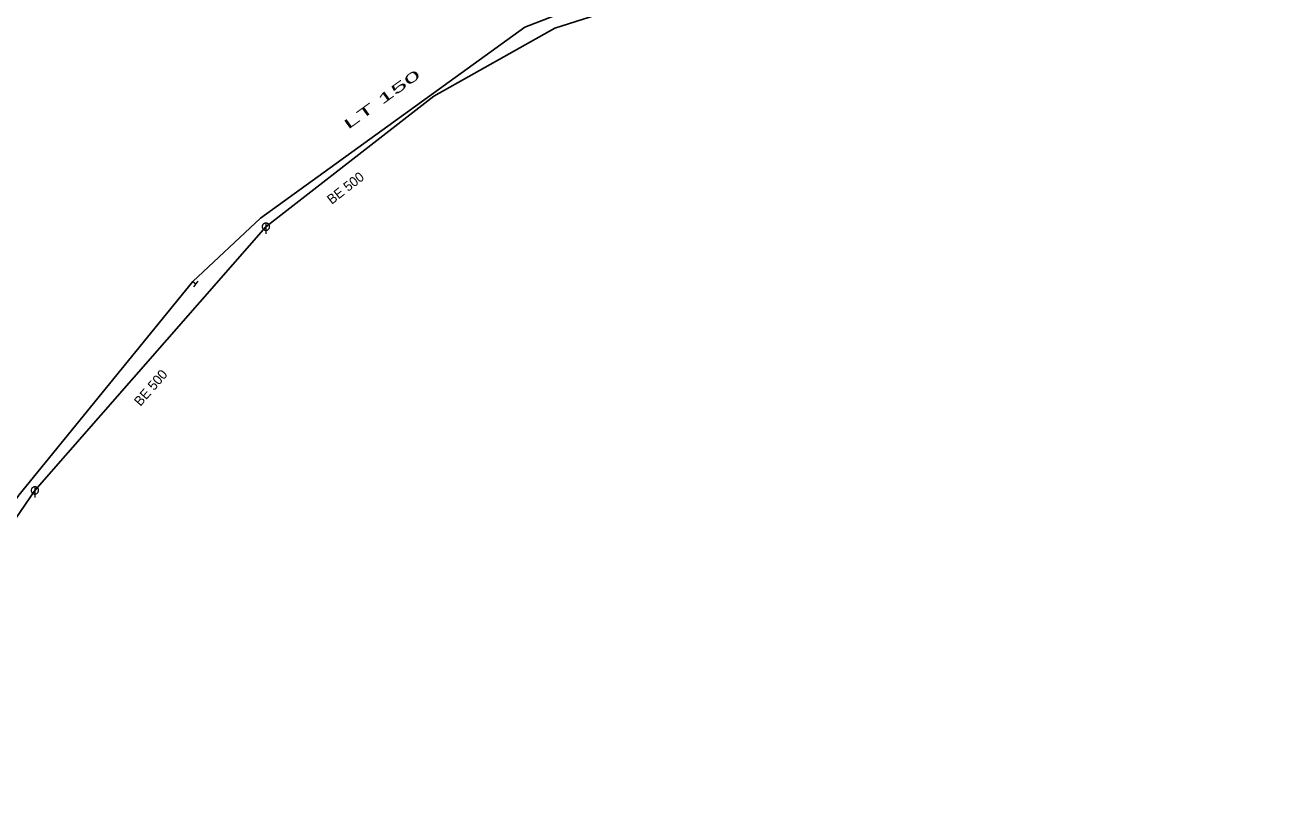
# Model space of a CAD drawing. Extents: x -687515 to -686506, y -974029 to -973461.
# Drawn here: x -687063.3 to -686976.8, y -973857.6 to -973804.9 of the extents above; entities that cross this region are included whole.
import ezdxf
from ezdxf.enums import TextEntityAlignment as Align

# ---------------------------------------------------------------- set-up
doc = ezdxf.new("R2010")
doc.units = 0
doc.header["$LTSCALE"] = 0.27
for name, color, linetype, lineweight in [('1', 7, 'Continuous', 13), ('14', 7, 'Continuous', 25), ('17', 7, 'Continuous', 25), ('22', 7, 'Continuous', 13), ('34', 7, 'Continuous', 13)]:
    doc.layers.add(name, color=color, linetype=linetype, lineweight=lineweight)

msp = doc.modelspace()

# ---------------------------------------------------------------- linework, layer by layer
at = {"layer": '14'}
for p, q in [((-687046.647, -973818.78), (-687062.584, -973836.971)), ((-687062.584, -973836.971), (-687076.719, -973857.559))]:
    msp.add_line(p, q, dxfattribs=at)
at = {"layer": '14', "lineweight": 13}
msp.add_line((-687051.693, -973822.548), (-687051.469, -973822.729), dxfattribs=at)
at = {"layer": '14'}
msp.add_lwpolyline([(-687012.736, -973800.616), (-687026.707, -973805.08), (-687035.055, -973809.776), (-687046.647, -973818.78)], dxfattribs=at)
at = {"layer": '17'}
msp.add_lwpolyline([(-687075.086, -973853.519), (-687063.695, -973837.3), (-687051.693, -973822.548), (-687047.027, -973818.188), (-687028.776, -973805.013), (-687019.272, -973801.323), (-687004.054, -973797.199), (-686987.892, -973793.361), (-686982.074, -973791.647), (-686976.761, -973790.276)], dxfattribs=at)
at = {"layer": '22'}
for p, q in [((-687046.646, -973818.528), (-687046.647, -973819.272)), ((-687062.583, -973836.719), (-687062.584, -973837.463))]:
    msp.add_line(p, q, dxfattribs=at)
for points in [[(-687046.395, -973818.78), (-687046.396, -973818.754), (-687046.4, -973818.728), (-687046.406, -973818.702), (-687046.416, -973818.678), (-687046.428, -973818.654), (-687046.442, -973818.632), (-687046.459, -973818.611), (-687046.477, -973818.593), (-687046.498, -973818.576), (-687046.52, -973818.562), (-687046.544, -973818.55), (-687046.568, -973818.54), (-687046.594, -973818.534), (-687046.62, -973818.53), (-687046.646, -973818.528), (-687046.672, -973818.529), (-687046.698, -973818.533), (-687046.724, -973818.539), (-687046.749, -973818.549), (-687046.772, -973818.561), (-687046.794, -973818.575), (-687046.815, -973818.592), (-687046.833, -973818.61), (-687046.85, -973818.631), (-687046.864, -973818.653), (-687046.876, -973818.677), (-687046.886, -973818.701), (-687046.893, -973818.727), (-687046.897, -973818.753), (-687046.899, -973818.779), (-687046.898, -973818.805), (-687046.894, -973818.831), (-687046.887, -973818.857), (-687046.877, -973818.882), (-687046.865, -973818.905), (-687046.851, -973818.927), (-687046.834, -973818.948), (-687046.816, -973818.966), (-687046.795, -973818.983), (-687046.773, -973818.997), (-687046.75, -973819.009), (-687046.725, -973819.019), (-687046.699, -973819.026), (-687046.673, -973819.03), (-687046.647, -973819.032), (-687046.621, -973819.031), (-687046.595, -973819.027), (-687046.569, -973819.02), (-687046.545, -973819.01), (-687046.521, -973818.998), (-687046.499, -973818.984), (-687046.478, -973818.967), (-687046.46, -973818.949), (-687046.443, -973818.928), (-687046.429, -973818.906), (-687046.417, -973818.883), (-687046.407, -973818.858), (-687046.401, -973818.832), (-687046.397, -973818.806)], [(-687062.332, -973836.971), (-687062.333, -973836.945), (-687062.337, -973836.919), (-687062.343, -973836.893), (-687062.353, -973836.869), (-687062.365, -973836.845), (-687062.379, -973836.823), (-687062.396, -973836.802), (-687062.414, -973836.784), (-687062.435, -973836.767), (-687062.457, -973836.753), (-687062.481, -973836.741), (-687062.505, -973836.731), (-687062.531, -973836.725), (-687062.557, -973836.721), (-687062.583, -973836.719), (-687062.609, -973836.72), (-687062.635, -973836.724), (-687062.661, -973836.73), (-687062.686, -973836.74), (-687062.709, -973836.752), (-687062.731, -973836.766), (-687062.752, -973836.783), (-687062.77, -973836.801), (-687062.787, -973836.822), (-687062.801, -973836.844), (-687062.813, -973836.868), (-687062.823, -973836.892), (-687062.83, -973836.918), (-687062.834, -973836.944), (-687062.836, -973836.97), (-687062.835, -973836.996), (-687062.831, -973837.022), (-687062.824, -973837.048), (-687062.814, -973837.073), (-687062.802, -973837.096), (-687062.788, -973837.118), (-687062.771, -973837.139), (-687062.753, -973837.157), (-687062.732, -973837.174), (-687062.71, -973837.188), (-687062.687, -973837.2), (-687062.662, -973837.21), (-687062.636, -973837.217), (-687062.61, -973837.221), (-687062.584, -973837.223), (-687062.558, -973837.222), (-687062.532, -973837.218), (-687062.506, -973837.211), (-687062.482, -973837.201), (-687062.458, -973837.189), (-687062.436, -973837.175), (-687062.415, -973837.158), (-687062.397, -973837.14), (-687062.38, -973837.119), (-687062.366, -973837.097), (-687062.354, -973837.074), (-687062.344, -973837.049), (-687062.338, -973837.023), (-687062.334, -973836.997)]]:
    msp.add_lwpolyline(points, close=True, dxfattribs=at)
at = {"layer": '34'}
msp.add_line((-687051.625, -973822.921), (-687051.312, -973822.536), dxfattribs=at)

# ---------------------------------------------------------------- texts
at = {"layer": '1', "width": 2.25}
msp.add_text('LT 150', height=0.6667, rotation=36, dxfattribs=at).set_placement((-687038.448, -973810.269), align=Align.CENTER)
at = {"layer": '1'}
for rotation, p in [(38, (-687040.951, -973816.374)), (49, (-687054.343, -973830.104))]:
    msp.add_text('BE 500', height=0.6667, rotation=rotation, dxfattribs=at).set_placement(p, align=Align.CENTER)

doc.saveas('drawing.dxf')
